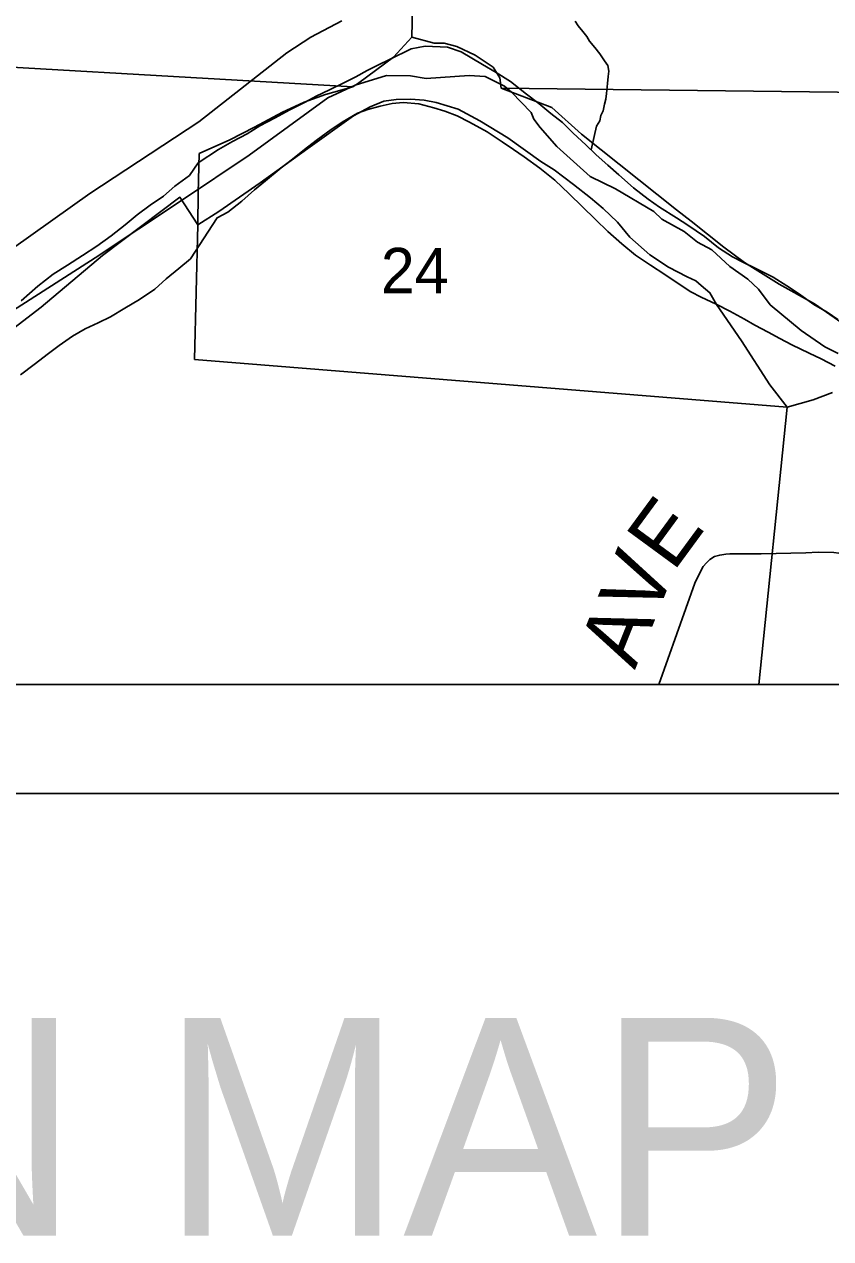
# Model space of a CAD drawing. Extents: x -7.5 to 26.5, y 3.5 to 25.5.
# Drawn here: x -1.714 to -0.973, y 17.091 to 18.207 of the extents above; entities that cross this region are included whole.
import ezdxf

# ---------------------------------------------------------------- set-up
doc = ezdxf.new("R2010")
doc.units = 0
for name, color, linetype in [('GM_X_Corporation', 7, 'Continuous'), ('GM_X_County_Road', 7, 'Continuous'), ('GM_X_County_Road_Text', 7, 'Continuous'), ('GM_X_Major_River', 7, 'Continuous'), ('GM_X_Minor_River', 7, 'Continuous'), ('GM_X_Section_Text', 7, 'Continuous'), ('GM_X_State_Route', 7, 'Continuous'), ('SH_Data', 7, 'Continuous'), ('SH_Text', 7, 'Continuous')]:
    doc.layers.add(name, color=color, linetype=linetype)

msp = doc.modelspace()

# ---------------------------------------------------------------- linework, layer by layer
at = {"layer": 'GM_X_Corporation'}
for points in [[(-5.2848, 19.2392), (-5.3003, 18.6476), (-5.3247, 17.7117), (-5.3276, 17.6), (1.4431, 17.6), (1.4431, 24.4)], [(-0.966, 17.9043), (-0.9784, 17.9104), (-1.0002, 17.9252), (-1.0286, 17.949), (-1.0392, 17.9634), (-1.0491, 17.9725), (-1.0658, 17.9841), (-1.0823, 17.9995), (-1.0954, 18.0064), (-1.1076, 18.0163), (-1.1281, 18.0277), (-1.1354, 18.0348), (-1.1708, 18.0554), (-1.1939, 18.0668), (-1.2245, 18.0945), (-1.2398, 18.1117), (-1.2456, 18.1195), (-1.2481, 18.1257), (-1.2664, 18.1442), (-1.2727, 18.1497), (-1.2906, 18.1587), (-1.3051, 18.1596), (-1.3446, 18.1568), (-1.359, 18.1592), (-1.381, 18.1596), (-1.4098, 18.1507), (-1.4349, 18.139), (-1.5073, 18.0864), (-1.5695, 18.0449), (-1.6488, 17.9921), (-1.7882, 17.9031)], [(-1.7882, 17.9031), (-1.6488, 17.9921), (-1.5695, 18.0449), (-1.5073, 18.0864), (-1.4349, 18.139), (-1.4098, 18.1507), (-1.381, 18.1596), (-1.359, 18.1592), (-1.3446, 18.1568), (-1.3051, 18.1596), (-1.2906, 18.1587), (-1.2727, 18.1497), (-1.2664, 18.1442), (-1.2481, 18.1257), (-1.2456, 18.1195), (-1.2398, 18.1117), (-1.2245, 18.0945), (-1.1939, 18.0668), (-1.1708, 18.0554), (-1.1354, 18.0348), (-1.1281, 18.0277), (-1.1076, 18.0163), (-1.0954, 18.0064), (-1.0823, 17.9995), (-1.0658, 17.9841), (-1.0491, 17.9725), (-1.0392, 17.9634), (-1.0286, 17.949), (-1.0002, 17.9252), (-0.9784, 17.9104), (-0.966, 17.9043)], [(-0.9627, 17.9325), (-0.988, 17.9498), (-1.0205, 17.968), (-1.0522, 17.9877), (-1.0712, 18.0018), (-1.1013, 18.0257), (-1.1147, 18.0362), (-1.202, 18.1058), (-1.2291, 18.1303), (-1.2757, 18.1481), (-0.3746, 18.1372)], [(-0.9714, 17.8683), (-0.989, 17.8616), (-1.013, 17.8549), (-1.0391, 17.6), (-0.0167, 17.6)], [(-2.0482, 17.6), (1.4431, 17.6)]]:
    msp.add_lwpolyline(points, dxfattribs=at)
for points in [[(-1.3364, 19.1437), (-1.3579, 18.1948), (-1.3746, 18.1766), (-1.4066, 18.1528), (-1.412, 18.1491), (-2.3477, 18.203), (-2.3216, 19.1609)], [(-0.3419, 19.1283), (-0.3746, 18.1372), (-1.2757, 18.1481), (-1.2769, 18.1576), (-1.2831, 18.1672), (-1.2995, 18.1782), (-1.3164, 18.1862), (-1.3281, 18.1892), (-1.3372, 18.1894), (-1.3579, 18.1948), (-1.3364, 19.1437)], [(-2.3653, 17.6), (-2.0344, 17.6), (-2.0162, 17.6469), (-1.9628, 17.7181), (-1.8826, 17.8072), (-1.7876, 17.8785), (-1.6985, 17.9468), (-1.6421, 17.9943), (-1.5709, 18.0477), (-1.5545, 18.0223), (-1.5541, 18.0516), (-1.5532, 18.0879), (-1.5251, 18.1005), (-1.5024, 18.1123), (-1.4766, 18.1259), (-1.4567, 18.135), (-1.4372, 18.1422), (-1.412, 18.1491), (-2.3477, 18.203)], [(-1.5545, 18.0223), (-1.5353, 18.0347), (-1.4971, 18.061), (-1.4535, 18.0926), (-1.4115, 18.1226), (-1.3962, 18.1309), (-1.3835, 18.1359), (-1.3721, 18.1376), (-1.3592, 18.138), (-1.3464, 18.1369), (-1.3355, 18.1348), (-1.3152, 18.1286), (-1.2953, 18.1179), (-1.2696, 18.1025), (-1.2394, 18.0805), (-1.2271, 18.073), (-1.2092, 18.0594), (-1.1936, 18.0472), (-1.1821, 18.0375), (-1.1688, 18.025), (-1.1577, 18.0111), (-1.1392, 17.9948), (-1.122, 17.9834), (-1.1048, 17.9746), (-1.097, 17.971), (-1.0921, 17.9667), (-1.084, 17.9601), (-1.0778, 17.9493), (-1.0551, 17.9158), (-1.0288, 17.8754), (-1.013, 17.8549), (-1.5575, 17.8988)], [(-2.0344, 17.6), (-1.0391, 17.6), (-1.013, 17.8549), (-1.5575, 17.8988), (-1.5545, 18.0223), (-1.5709, 18.0477), (-1.6421, 17.9943), (-1.6985, 17.9468), (-1.7876, 17.8785), (-1.8826, 17.8072), (-1.9628, 17.7181), (-2.0162, 17.6469)]]:
    msp.add_lwpolyline(points, close=True, dxfattribs=at)
at = {"layer": 'GM_X_County_Road'}
msp.add_lwpolyline([(-1.131, 17.6), (-1.0978, 17.6932), (-1.0936, 17.7021), (-1.0903, 17.7085), (-1.0871, 17.712), (-1.0841, 17.7149), (-1.0797, 17.7176), (-1.0749, 17.719), (-1.0692, 17.7199), (-1.0658, 17.7203), (-1.0368, 17.7203), (-0.9957, 17.7211), (-0.9844, 17.7216), (-0.9701, 17.7214), (-0.9609, 17.7202), (-0.8832, 17.7124)], dxfattribs=at)
at = {"layer": 'GM_X_Major_River'}
for points in [[(-0.9665, 17.9354), (-0.9762, 17.9421), (-0.9885, 17.9493), (-1.0026, 17.9593), (-1.0134, 17.9664), (-1.026, 17.9744), (-1.0425, 17.9825), (-1.053, 17.9878), (-1.0631, 17.9931), (-1.0761, 18.0014), (-1.0891, 18.0117), (-1.1043, 18.0221), (-1.1147, 18.0288), (-1.1304, 18.0388), (-1.1408, 18.046), (-1.1541, 18.0563), (-1.1678, 18.0685), (-1.1778, 18.0772), (-1.1885, 18.0866), (-1.1981, 18.096), (-1.2095, 18.1066), (-1.2195, 18.1164), (-1.2302, 18.1248), (-1.2413, 18.1338), (-1.2525, 18.1425), (-1.2673, 18.154), (-1.2803, 18.1624), (-1.293, 18.1696), (-1.3027, 18.1756), (-1.3124, 18.1813), (-1.3252, 18.1858), (-1.3457, 18.1865), (-1.3583, 18.1842), (-1.3783, 18.1742), (-1.3891, 18.1692), (-1.3988, 18.1642), (-1.4092, 18.1584), (-1.4208, 18.1527), (-1.4335, 18.1466), (-1.4458, 18.1406), (-1.4559, 18.1352), (-1.4698, 18.128), (-1.484, 18.1205), (-1.4976, 18.1133), (-1.5092, 18.1061), (-1.5227, 18.0989), (-1.5354, 18.0917), (-1.554, 18.0794)], [(-1.5613, 17.9911), (-1.5366, 18.029), (-1.527, 18.0341), (-1.5141, 18.0443), (-1.5024, 18.0546), (-1.4923, 18.063), (-1.4779, 18.0747), (-1.4674, 18.0827), (-1.4565, 18.0915), (-1.4456, 18.0999), (-1.432, 18.1101), (-1.4219, 18.1167), (-1.4079, 18.125), (-1.3983, 18.1285), (-1.3869, 18.1315), (-1.3758, 18.1338), (-1.3659, 18.1347), (-1.3515, 18.1335), (-1.3375, 18.13), (-1.3274, 18.127), (-1.3161, 18.1225), (-1.3049, 18.1168), (-1.2885, 18.1079), (-1.2747, 18.0988), (-1.2643, 18.0916), (-1.2546, 18.0849), (-1.2401, 18.0745), (-1.2264, 18.0635), (-1.2132, 18.0509), (-1.1892, 18.0274), (-1.1778, 18.0164), (-1.1648, 18.005), (-1.1522, 17.9947), (-1.1385, 17.9855), (-1.1255, 17.9768), (-1.1132, 17.9684), (-1.1016, 17.9608), (-1.0919, 17.956), (-1.0781, 17.9495), (-1.0657, 17.943), (-1.0523, 17.9357), (-1.0426, 17.9301), (-1.0306, 17.9237), (-1.0198, 17.918), (-1.0086, 17.9123), (-0.9929, 17.9046), (-0.9817, 17.8994), (-0.969, 17.8925)], [(-1.554, 18.0794), (-1.562, 18.0678), (-1.5756, 18.058), (-1.5861, 18.0488), (-1.5982, 18.0405), (-1.6102, 18.0317), (-1.6211, 18.0225), (-1.634, 18.0123), (-1.6472, 18.0028), (-1.6604, 17.9941), (-1.6743, 17.9855), (-1.6875, 17.9771), (-1.7015, 17.9662), (-1.7167, 17.9526)], [(-1.7173, 17.8846), (-1.7049, 17.8941), (-1.6916, 17.9043), (-1.6819, 17.9116), (-1.6695, 17.92), (-1.6579, 17.9268), (-1.6459, 17.9325), (-1.6348, 17.9379), (-1.6216, 17.9458), (-1.6081, 17.9538), (-1.5941, 17.9632), (-1.5836, 17.9728), (-1.5719, 17.9823), (-1.5613, 17.9911)]]:
    msp.add_lwpolyline(points, dxfattribs=at)
at = {"layer": 'GM_X_Minor_River'}
msp.add_lwpolyline([(-1.1932, 18.0912), (-1.1881, 18.113), (-1.1852, 18.1179), (-1.1843, 18.1228), (-1.1822, 18.1273), (-1.1809, 18.1333), (-1.1796, 18.1378), (-1.179, 18.1431), (-1.178, 18.1522), (-1.1774, 18.1586), (-1.1768, 18.1636), (-1.1778, 18.1689), (-1.1807, 18.1732), (-1.185, 18.1794), (-1.1897, 18.1853), (-1.1945, 18.1911), (-1.197, 18.1954), (-1.2006, 18.2001), (-1.205, 18.2052), (-1.2079, 18.2095)], dxfattribs=at)
at = {"layer": 'GM_X_State_Route'}
msp.add_lwpolyline([(-1.8326, 17.924), (-1.6536, 18.0511), (-1.5535, 18.117), (-1.4728, 18.1805), (-1.4505, 18.1947), (-1.422, 18.21)], dxfattribs=at)
at = {"layer": 'SH_Data'}
for p, q in [((-5.3569, 17.6), (1.4431, 17.6)), ((-5.4569, 17.5), (1.5431, 17.5))]:
    msp.add_line(p, q, dxfattribs=at)

# ---------------------------------------------------------------- texts
at = {"layer": 'GM_X_County_Road_Text'}
for s, rotation, p in [('E', 53.7378, (-1.1177, 17.7027)), ('V', 68.1571, (-1.1344, 17.6595)), ('A', 68.2816, (-1.1529, 17.6131))]:
    msp.add_text(s, height=0.0568, rotation=rotation, dxfattribs=at).set_placement(p)
at = {"layer": 'GM_X_Section_Text'}
msp.add_text('24', height=0.04186, rotation=0, dxfattribs=at).set_placement((-1.3863, 17.9594))
at = {"layer": 'SH_Text'}
msp.add_text('LOCATION MAP', height=0.2, dxfattribs=at).set_placement((-3.03, 17.0938))

doc.saveas('drawing.dxf')
